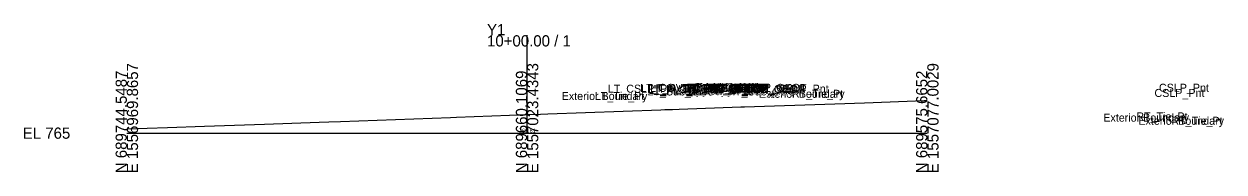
# Model space of a CAD drawing. Extents: x -26 to 303, y -10 to 5005.
# Drawn here: x -25.7 to 274.1, y -9.7 to 27.2 of the extents above; entities that cross this region are included whole.
import ezdxf

# ---------------------------------------------------------------- set-up
doc = ezdxf.new("R2010")
doc.units = 0
for name, color, linetype in [('Default', 7, 'Continuous'), ('Exist Cross Section Cell', 7, 'Continuous'), ('Exist XS Center Line Elevation Label', 7, 'Continuous'), ('Exist XS Ground Line', 7, 'Continuous')]:
    doc.layers.add(name, color=color, linetype=linetype)

msp = doc.modelspace()

# ---------------------------------------------------------------- linework, layer by layer
at = {"layer": 'Exist Cross Section Cell'}
for p, q in [((100, 0), (100, 24.43)), ((0, 0), (100, 0)), ((100, 0), (200, 0))]:
    msp.add_line(p, q, dxfattribs=at)
at = {"layer": 'Exist XS Ground Line'}
msp.add_lwpolyline([(0, 1.09), (10.16, 1.42), (19.4, 1.74), (34.38, 2.26), (48.05, 2.75), (50.45, 2.82), (53.35, 2.93), (80.9, 3.92), (82.37, 3.97), (100, 4.61), (103.33, 4.73), (105.18, 4.8), (133.38, 5.82), (134.45, 5.86), (136.37, 5.94), (137.96, 6), (153.37, 6.53), (154.34, 6.56), (176.89, 7.35), (184.32, 7.6), (199.21, 8.12), (200, 8.14)], dxfattribs=at)

# ---------------------------------------------------------------- texts
at = {"layer": 'Default'}
for s, height, p in [('LT_CSLP_Pnt', 2, (120.17, 10.09)), ('LT_CG_Top_BOC', 2, (128.28, 10.29)), ('LT_PV2_OEOT', 2, (130.17, 10.04)), ('LT_PV1_OEOT', 2, (130.74, 10.29)), ('RT_PV2_OEEOP', 2, (139.26, 10.24)), ('RT_PV3_OEEOP', 2, (139.26, 9.99)), ('LT_PV2_OEEOP', 2, (139.31, 10.24)), ('LT_PV3_OEEOP', 2, (139.31, 9.99)), ('RT_PV1_OEEOP', 2, (139.83, 10.36)), ('LT_PV1_OEEOP', 2, (139.87, 10.36)), ('RT_PV2_IEEOP', 2, (139.91, 10.24)), ('LT_PV2_IEEOP', 2, (139.95, 10.24)), ('RT_PV1_IEEOP', 2, (140.47, 10.36)), ('LT_PV1_IEEOP', 2, (140.52, 10.36)), ('RT_PV2_PGL', 2, (141.17, 10.24)), ('LT_PV2_PGL', 2, (141.21, 10.24)), ('RT_PV1_PGL', 2, (141.73, 10.49)), ('LT_PV1_PGL', 2, (141.78, 10.49)), ('RT_PV2_OEOT', 2, (150.13, 10.04)), ('RT_PV1_OEOT', 2, (150.69, 10.29)), ('CSLP_Pnt', 2, (162.87, 10.09)), ('CSLP_Pnt', 2, (257.88, 10.33)), ('Exterior Boundary', 2, (108.65, 8.26)), ('LT_Tie_Pt', 2, (116.95, 8.26)), ('LT_Sub_OEOT', 2, (130.08, 9.41)), ('LT_PV3_OEOT', 2, (130.17, 9.79)), ('RT_Sub_OEEOP', 2, (139.17, 9.61)), ('LT_Sub_OEEOP', 2, (139.21, 9.61)), ('RT_Sub_OEOT', 2, (150.03, 9.41)), ('RT_PV3_OEOT', 2, (150.13, 9.79)), ('Exterior Boundary', 2, (157.93, 8.82)), ('RT_Tie_Pt', 2, (166.18, 8.82)), ('CSLP_Pnt', 2, (256.75, 9.03)), ('Exterior Boundary', 2, (243.97, 2.87)), ('RT_Tie_Pt', 2, (252.22, 3.17)), ('Exterior Boundary', 2, (252.73, 2.09)), ('RT_Tie_Pt', 2, (260.98, 2.09)), ('-', 0.0001, (0, 0))]:
    msp.add_text(s, height=height, dxfattribs=at).set_placement(p)
at = {"layer": 'Exist Cross Section Cell'}
for s, p in [('Y1', (90, 24.43)), ('10+00.00 / 1', (90, 21.63)), ('EL 765', (-26, -1.4))]:
    msp.add_text(s, height=2.8, dxfattribs=at).set_placement(p)
for s, p in [('N 689744.5487', (0, -10)), ('E 1556969.8657', (2.8, -10)), ('N 689660.1069', (100, -10)), ('E 1557023.4343', (102.8, -10)), ('N 689575.6652', (200, -10)), ('E 1557077.0029', (202.8, -10))]:
    msp.add_text(s, height=2.8, rotation=90, dxfattribs=at).set_placement(p)
at = {"layer": 'Exist XS Center Line Elevation Label'}
msp.add_text('769.61', height=1, dxfattribs=at).set_placement((97.94, 0.11))

doc.saveas('drawing.dxf')
